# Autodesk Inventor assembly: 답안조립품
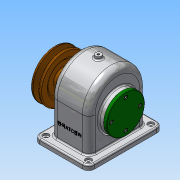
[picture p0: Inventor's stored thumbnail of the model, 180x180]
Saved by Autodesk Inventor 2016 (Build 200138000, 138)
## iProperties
Created: 2018-08
Part Number: 답안조립품
Material: 일반
Document SubType Name: Assembly
Designer: Administrator
Author: Administrator
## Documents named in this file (14)
- C:\Users\Administrator\Desktop\480811V1006\답안조립품.iam
- C:\Users\Administrator\Desktop\480811V1006\본체.ipt
- C:\Users\Administrator\Desktop\480811V1006\축.ipt
- C:\Users\Administrator\Desktop\480811V1006\스퍼기어.ipt
- C:\Users\Administrator\Desktop\480811V1006\베어링 6203.ipt
- C:\Users\Administrator\Desktop\480811V1006\부시.ipt
- C:\Users\Administrator\Desktop\480811V1006\앞커버.ipt
- C:\Users\Administrator\Desktop\480811V1006\뒤커버.ipt
- C:\Users\Administrator\Desktop\480811V1006\오일 실 28 40 8.ipt
- C:\Users\Administrator\Desktop\480811V1006\V-벨트풀리.ipt
- C:\Users\Administrator\Desktop\480811V1006\키 6x6x22.ipt
- C:\Users\Administrator\Desktop\480811V1006\키 5x5x18.ipt
- C:\Users\Administrator\Desktop\480811V1006\멈춤나사 M4.ipt
- C:\Users\Administrator\Desktop\480811V1006\볼트 M4.ipt
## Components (1 placed, 1 different names)
1. V-벨트풀리:1
